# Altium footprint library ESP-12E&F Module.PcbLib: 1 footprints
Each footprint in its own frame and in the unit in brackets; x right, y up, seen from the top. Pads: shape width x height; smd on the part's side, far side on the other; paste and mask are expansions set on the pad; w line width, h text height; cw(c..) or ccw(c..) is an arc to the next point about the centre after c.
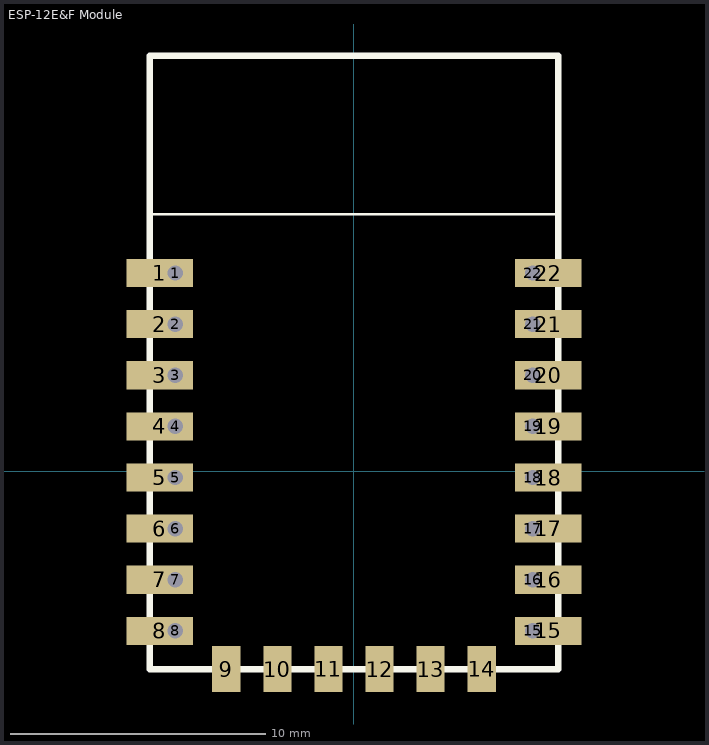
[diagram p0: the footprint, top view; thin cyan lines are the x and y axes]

## ESP-12E&F Module [mm]
pads (38):
  rect 2.6x1.1 smd: 1(-7.6,7.75) 2(-7.6,5.75) 3(-7.6,3.75) 4(-7.6,1.75) 5(-7.6,-0.25) 6(-7.6,-2.25) 7(-7.6,-4.25) 8(-7.6,-6.25) 15(7.6,-6.25) 16(7.6,-4.25) 17(7.6,-2.25) 18(7.6,-0.25) 19(7.6,1.75) 20(7.6,3.75) 21(7.6,5.75) 22(7.6,7.75)
  rect 0.762x1 hole 0.6: 1(-7,7.75) 7(-7,-4.25)
  rect 0.762x1 / inner rect 0.762x1 / far side rect 1x1 hole 0.6: 2(-7,5.75) 3(-7,3.75) 4(-7,1.75) 5(-7,-0.25) 6(-7,-2.25) 8(-7,-6.25) 15(7,-6.25) 16(7,-4.25) 17(7,-2.25) 18(7,-0.25) 19(7,1.75) 20(7,3.75) 21(7,5.75) 22(7,7.75)
  rect 1.1x1.8 smd: 9(-5,-7.75) 10(-3,-7.75) 11(-1,-7.75) 12(1,-7.75) 13(3,-7.75) 14(5,-7.75)
Top Overlay:
  lines w0.1: -8,10.05 8,10.05
  lines w0.254: -8,-7.75 8,-7.75 8,16.25 -8,16.25 -8,-7.75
